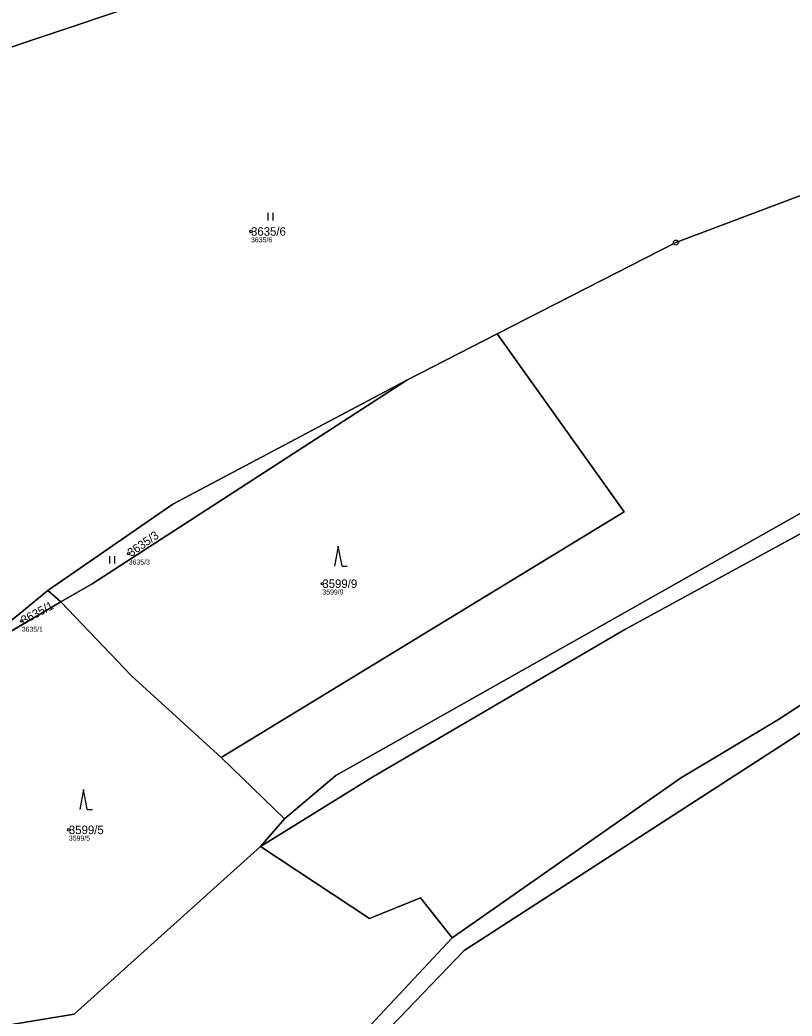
# Model space of a CAD drawing. Extents: x -761174 to -757114, y -1063806 to -1059397.
# Drawn here: x -760063.2 to -759909, y -1062519.8 to -1062320.9 of the extents above; entities that cross this region are included whole.
import ezdxf

# ---------------------------------------------------------------- set-up
doc = ezdxf.new("R2010")
doc.units = 0
for name, color, linetype in [('Definiční body', 7, 'Continuous'), ('Hranice parcel', 7, 'Continuous'), ('Parcelní čísla', 7, 'Continuous'), ('Polygon parcely', 7, 'Continuous'), ('Značky bodu BP', 7, 'Continuous'), ('Značky kultur', 7, 'Continuous')]:
    doc.layers.add(name, color=color, linetype=linetype)

msp = doc.modelspace()

# ---------------------------------------------------------------- linework, layer by layer
at = {"layer": 'Definiční body'}
for centre in [(-760017.01, -1062363.18), (-760041.44, -1062427.51), (-760002.77, -1062433.49), (-760062.79, -1062440.92), (-760053.38, -1062482.63)]:
    msp.add_circle(centre, 0.25, dxfattribs=at)
at = {"layer": 'Hranice parcel'}
for p, q in [((-759967.88, -1062383.64), (-759985.92, -1062392.87)), ((-760057.57, -1062434.83), (-760074.07, -1062448.33)), ((-760054.99, -1062437.14), (-760057.57, -1062434.83)), ((-760054.99, -1062437.14), (-760074.07, -1062448.33)), ((-760010.32, -1062480.46), (-760023, -1062468.21)), ((-760015.1, -1062485.98), (-760010.32, -1062480.46))]:
    msp.add_line(p, q, dxfattribs=at)
for points in [[(-759785.19, -1062290.87), (-759812.06, -1062312.74), (-759841.45, -1062329.06), (-759887.14, -1062348.41), (-759932.19, -1062365.38), (-759967.88, -1062383.64)], [(-760098.41, -1062337.59), (-760027.57, -1062313.78), (-759968.14, -1062295.03)], [(-760020.59, -1062648.57), (-759995.77, -1062595.56), (-759991.2, -1062568.04), (-759996.63, -1062541.3), (-759992.35, -1062525.36), (-759974.46, -1062506.7), (-759909.51, -1062464.71), (-759859.16, -1062431.43), (-759834.95, -1062413.73), (-759801.17, -1062385.56), (-759794.9, -1062381.81), (-759778.11, -1062375.37), (-759761.36, -1062358.58), (-759747.99, -1062337.03), (-759743.43, -1062321.15), (-759739.84, -1062308.74), (-759740.67, -1062299.37)], [(-759804.96, -1062384.25), (-759797.09, -1062376.3), (-759788.32, -1062361.07), (-759795.31, -1062348.22), (-759836.53, -1062377.86), (-759869.21, -1062399.78), (-759880.79, -1062407.51), (-759905.53, -1062422.51), (-759942.36, -1062442.65), (-759992.57, -1062471.95), (-760015.1, -1062485.98)], [(-760010.32, -1062480.46), (-760000.07, -1062471.78), (-759958.26, -1062448.21), (-759890.08, -1062409.72), (-759837.94, -1062374.87)], [(-760023, -1062468.21), (-759942.48, -1062419.16), (-759967.88, -1062383.64)], [(-759804.96, -1062384.25), (-759833.11, -1062407.31), (-759857.38, -1062424.92), (-759881.2, -1062440.68), (-759911.67, -1062460.58), (-759931.27, -1062472.34), (-759976.87, -1062504.2)], [(-759985.92, -1062392.87), (-760032.66, -1062417.64), (-760057.57, -1062434.83)], [(-759985.92, -1062392.87), (-760048.76, -1062433.49), (-760054.99, -1062437.14)], [(-760023, -1062468.21), (-760040.85, -1062451.91), (-760054.99, -1062437.14)], [(-760015.1, -1062485.98), (-760052.34, -1062519.44), (-760066.85, -1062521.81), (-760078.74, -1062529.63)], [(-759976.87, -1062504.2), (-759983.21, -1062496.23), (-759993.35, -1062500.32), (-760015.1, -1062485.98)], [(-759976.87, -1062504.2), (-759995.07, -1062523.66), (-760000.01, -1062541.54), (-759995.22, -1062568.65), (-759998.76, -1062595.2), (-760022.89, -1062646.24), (-760056.5, -1062694.96), (-760072.49, -1062710), (-760095, -1062741.4)]]:
    msp.add_lwpolyline(points, dxfattribs=at)
at = {"layer": 'Polygon parcely'}
for points in [[(-760098.41, -1062337.59), (-760027.57, -1062313.78), (-759968.14, -1062295.03), (-759952.13, -1062262.89), (-760046.65, -1062249.38), (-760064.78, -1062278.38), (-760083.35, -1062318.15)], [(-759932.19, -1062365.38), (-759967.88, -1062383.64), (-759942.48, -1062419.16), (-760023, -1062468.21), (-760010.32, -1062480.46), (-760000.07, -1062471.78), (-759958.26, -1062448.21), (-759890.08, -1062409.72), (-759837.94, -1062374.87), (-759850.99, -1062357.55), (-759807.29, -1062328.11), (-759811.57, -1062319.1), (-759784.56, -1062302.86), (-759778.43, -1062294.67), (-759779.89, -1062284.06), (-759785.19, -1062290.87), (-759812.06, -1062312.74), (-759841.45, -1062329.06), (-759887.14, -1062348.41)], [(-759795.31, -1062348.22), (-759836.53, -1062377.86), (-759869.21, -1062399.78), (-759880.79, -1062407.51), (-759905.53, -1062422.51), (-759942.36, -1062442.65), (-759992.57, -1062471.95), (-760015.1, -1062485.98), (-759993.35, -1062500.32), (-759983.21, -1062496.23), (-759976.87, -1062504.2), (-759931.27, -1062472.34), (-759911.67, -1062460.58), (-759881.2, -1062440.68), (-759857.38, -1062424.92), (-759833.11, -1062407.31), (-759804.96, -1062384.25), (-759797.09, -1062376.3), (-759788.32, -1062361.07)], [(-759942.48, -1062419.16), (-759967.88, -1062383.64), (-759985.92, -1062392.87), (-760048.76, -1062433.49), (-760054.99, -1062437.14), (-760040.85, -1062451.91), (-760023, -1062468.21)], [(-760032.66, -1062417.64), (-760057.57, -1062434.83), (-760054.99, -1062437.14), (-760048.76, -1062433.49), (-759985.92, -1062392.87)], [(-760074.07, -1062448.33), (-760054.99, -1062437.14), (-760057.57, -1062434.83)], [(-760070.2, -1062478.25), (-760078.09, -1062526.39), (-760078.74, -1062529.63), (-760066.85, -1062521.81), (-760052.34, -1062519.44), (-760015.1, -1062485.98), (-760010.32, -1062480.46), (-760023, -1062468.21), (-760040.85, -1062451.91), (-760054.99, -1062437.14), (-760074.07, -1062448.33), (-760073.36, -1062453.25)], [(-760117.35, -1062646.59), (-760124.66, -1062690), (-760123.2, -1062714.36), (-760129.45, -1062742.99), (-760126.88, -1062755.51), (-760095, -1062741.4), (-760072.49, -1062710), (-760056.5, -1062694.96), (-760022.89, -1062646.24), (-759998.76, -1062595.2), (-759995.22, -1062568.65), (-760000.01, -1062541.54), (-759995.07, -1062523.66), (-759976.87, -1062504.2), (-759983.21, -1062496.23), (-759993.35, -1062500.32), (-760015.1, -1062485.98), (-760052.34, -1062519.44), (-760066.85, -1062521.81), (-760078.74, -1062529.63), (-760083.24, -1062552.25), (-760091.15, -1062580.69), (-760103.33, -1062611.24)]]:
    msp.add_lwpolyline(points, close=True, dxfattribs=at)
for points in [[(-759743.66, -1062306.91), (-759750.82, -1062334.23), (-759753.96, -1062339.82), (-759764.09, -1062355.43), (-759780.18, -1062372.22), (-759794.64, -1062378.4), (-759797.46, -1062379.2), (-759804.96, -1062384.25), (-759833.11, -1062407.31), (-759857.38, -1062424.92), (-759881.2, -1062440.68), (-759911.67, -1062460.58), (-759931.27, -1062472.34), (-759976.87, -1062504.2), (-759995.07, -1062523.66), (-760000.01, -1062541.54), (-759995.22, -1062568.65), (-759998.76, -1062595.2), (-760022.89, -1062646.24), (-760056.5, -1062694.96)], [(-760020.59, -1062648.57), (-759995.77, -1062595.56), (-759991.2, -1062568.04), (-759996.63, -1062541.3), (-759992.35, -1062525.36), (-759974.46, -1062506.7), (-759909.51, -1062464.71), (-759859.16, -1062431.43), (-759834.95, -1062413.73), (-759801.17, -1062385.56), (-759794.9, -1062381.81), (-759778.11, -1062375.37), (-759761.36, -1062358.58), (-759747.99, -1062337.03), (-759743.43, -1062321.15), (-759739.84, -1062308.74)], [(-759739.84, -1062308.74), (-759743.43, -1062321.15), (-759747.99, -1062337.03), (-759761.36, -1062358.58), (-759778.11, -1062375.37), (-759794.9, -1062381.81), (-759801.17, -1062385.56), (-759834.95, -1062413.73), (-759859.16, -1062431.43), (-759909.51, -1062464.71), (-759974.46, -1062506.7), (-759992.35, -1062525.36), (-759996.63, -1062541.3), (-759991.2, -1062568.04), (-759995.77, -1062595.56), (-760020.59, -1062648.57)], [(-760027.57, -1062313.78), (-760098.41, -1062337.59), (-760098.03, -1062340.02), (-760101.17, -1062355.06), (-760098.44, -1062371.3), (-760086.12, -1062406.45), (-760074.07, -1062448.33), (-760057.57, -1062434.83), (-760032.66, -1062417.64), (-759985.92, -1062392.87), (-759967.88, -1062383.64), (-759932.19, -1062365.38), (-759887.14, -1062348.41), (-759841.45, -1062329.06), (-759812.06, -1062312.74)], [(-759890.08, -1062409.72), (-759958.26, -1062448.21), (-760000.07, -1062471.78), (-760010.32, -1062480.46), (-760015.1, -1062485.98), (-759992.57, -1062471.95), (-759942.36, -1062442.65), (-759905.53, -1062422.51)]]:
    msp.add_lwpolyline(points, dxfattribs=at)
at = {"layer": 'Značky bodu BP'}
for radius in [0.5, 0.0303]:
    msp.add_circle((-759932.19, -1062365.38), radius, dxfattribs=at)
at = {"layer": 'Značky kultur'}
for p, q in [((-760013.59, -1062360.98), (-760013.59, -1062359.48)), ((-760012.59, -1062360.98), (-760012.59, -1062359.48)), ((-759999.59, -1062426.01), (-760000.34, -1062430.01)), ((-759998.84, -1062430.01), (-759999.59, -1062426.01)), ((-760045.21, -1062429.48), (-760045.21, -1062427.98)), ((-760044.21, -1062429.48), (-760044.21, -1062427.98)), ((-759998.84, -1062430.01), (-759997.84, -1062430.01)), ((-760050.45, -1062474.6), (-760051.2, -1062478.6)), ((-760049.7, -1062478.6), (-760050.45, -1062474.6)), ((-760049.7, -1062478.6), (-760048.7, -1062478.6))]:
    msp.add_line(p, q, dxfattribs=at)

# ---------------------------------------------------------------- texts
at = {"layer": 'Definiční body'}
for s, p in [('3635/6', (-760017.01, -1062365.34)), ('3635/3', (-760041.44, -1062429.67)), ('3599/9', (-760002.77, -1062435.65)), ('3635/1', (-760062.79, -1062443.08)), ('3599/5', (-760053.38, -1062484.79))]:
    msp.add_text(s, height=1, dxfattribs=at).set_placement(p)
at = {"layer": 'Parcelní čísla'}
for s, p in [('3635/6', (-760017.01, -1062364.03)), ('3599/9', (-760002.77, -1062434.34)), ('3599/5', (-760053.38, -1062483.48))]:
    msp.add_text(s, height=1.7, dxfattribs=at).set_placement(p)
for s, rotation, p in [('3635/3', 35, (-760040.95, -1062428.21)), ('3635/1', 28, (-760062.39, -1062441.67))]:
    msp.add_text(s, height=1.7, rotation=rotation, dxfattribs=at).set_placement(p)

doc.saveas('drawing.dxf')
